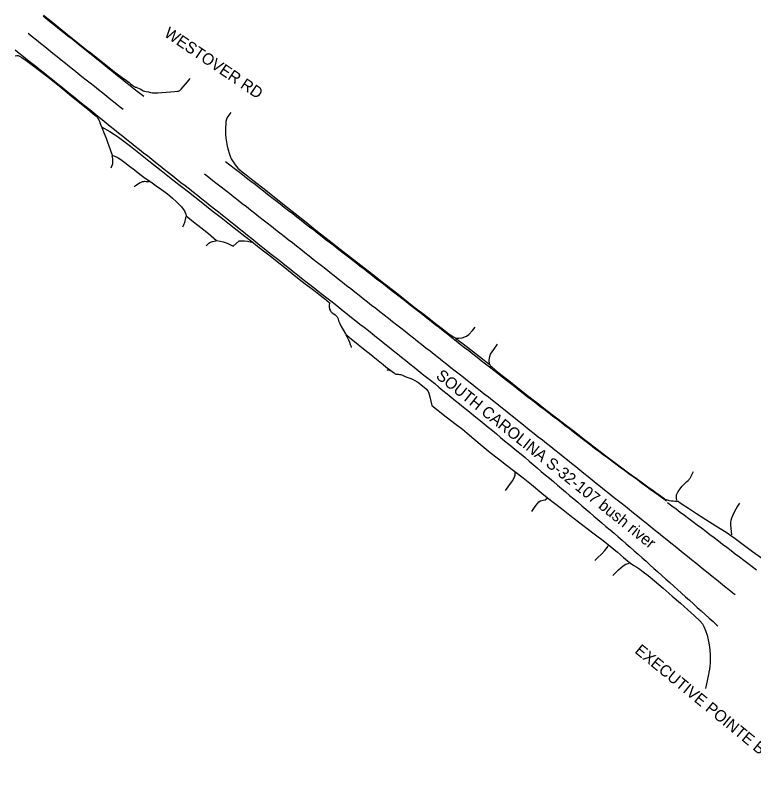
# Model space of a CAD drawing. Extents: x 1961683 to 1977751, y 798292 to 805767.
# Drawn here: x 1961690 to 1962037.9, y 800432.2 to 800788.3 of the extents above; entities that cross this region are included whole.
import ezdxf

# ---------------------------------------------------------------- set-up
doc = ezdxf.new("R2010")
doc.units = 0
for name, color, linetype in [('RD_EX_Road', 7, 'Continuous'), ('RD_EX_Road_Paint', 7, 'Continuous'), ('RD_TX_RoadID', 7, 'Continuous')]:
    doc.layers.add(name, color=color, linetype=linetype)

msp = doc.modelspace()

# ---------------------------------------------------------------- linework, layer by layer
at = {"layer": 'RD_EX_Road'}
for points in [[(1961703.41, 800788.33), (1961706.97, 800785.44), (1961713.96, 800779.79), (1961719.51, 800775.3), (1961724.42, 800771.33), (1961725.08, 800771.06), (1961732.71, 800765), (1961737.53, 800761.22), (1961740.46, 800758.97), (1961742.41, 800757.5), (1961743.68, 800756.55), (1961744.6, 800755.83), (1961745.28, 800755.29), (1961745.84, 800754.88), (1961746.34, 800754.6), (1961746.57, 800754.5), (1961747.03, 800754.38), (1961747.66, 800754.17), (1961748.45, 800753.85), (1961749.2, 800753.46), (1961749.86, 800753.02), (1961750.34, 800752.73), (1961750.52, 800752.65), (1961750.99, 800752.52), (1961751.81, 800752.35), (1961752.79, 800752.16), (1961753.78, 800751.93), (1961754.59, 800751.75), (1961755.05, 800751.69), (1961755.74, 800751.71), (1961757.24, 800751.79), (1961759.17, 800751.91), (1961761.16, 800752.05), (1961763.15, 800752.2), (1961765.07, 800752.35), (1961766.57, 800752.52), (1961767.05, 800752.62), (1961767.33, 800752.71), (1961767.56, 800752.87), (1961768.22, 800753.5), (1961769.24, 800754.66), (1961771.14, 800756.96), (1961772.45, 800758.56)], [(1961690.12, 800769.16), (1961690.78, 800769.36), (1961691.04, 800769.39), (1961691.27, 800769.38), (1961691.5, 800769.32), (1961692.15, 800769.03), (1961693.16, 800768.44), (1961695.19, 800767.05), (1961698.29, 800764.8), (1961702.19, 800761.83), (1961706.78, 800758.21), (1961711.65, 800754.29), (1961716.64, 800750.22), (1961721.26, 800746.47), (1961725.26, 800743.26), (1961727.62, 800741.32), (1961728.11, 800740.87), (1961728.61, 800740.3), (1961729.02, 800739.67), (1961729.39, 800738.99), (1961729.74, 800738.26), (1961730.15, 800737.28), (1961730.73, 800735.82), (1961734.57, 800733.53), (1961736.88, 800732.13), (1961738.75, 800730.89), (1961741.25, 800729.07), (1961744.43, 800726.64), (1961748.32, 800723.57), (1961753.06, 800719.79), (1961758.81, 800715.22), (1961765.14, 800710.22), (1961771.61, 800705.16), (1961777.67, 800700.42), (1961782.74, 800696.44), (1961787.08, 800693.03), (1961790.95, 800690.01), (1961794.57, 800687.19), (1961798.15, 800684.36), (1961801.44, 800681.74), (1961804.22, 800679.57), (1961806.94, 800677.46), (1961810.07, 800675), (1961813.46, 800672.31), (1961817, 800669.48), (1961820.51, 800666.67), (1961823.83, 800664.03), (1961826.68, 800661.83), (1961828.8, 800660.35), (1961830.74, 800658.96), (1961833.07, 800657.05), (1961835.66, 800654.89), (1961837.91, 800653.13), (1961838.02, 800653.05), (1961838.07, 800652.95), (1961838.07, 800652.86), (1961837.95, 800651.72), (1961837.94, 800651.23), (1961837.98, 800650.8), (1961838.05, 800650.39), (1961838.16, 800649.99), (1961838.5, 800649.21), (1961838.73, 800648.84), (1961839, 800648.5), (1961839.33, 800648.19), (1961840.08, 800647.67), (1961840.71, 800647.23), (1961841.18, 800646.87), (1961841.54, 800646.5), (1961841.68, 800646.32), (1961841.82, 800646.09), (1961842.09, 800645.42), (1961842.39, 800644.45), (1961842.89, 800643.26), (1961843.62, 800641.84), (1961844.53, 800640.17), (1961845.57, 800638.33), (1961846.3, 800637.67), (1961847.27, 800636.84), (1961848.47, 800635.84), (1961849.92, 800634.66), (1961851.52, 800633.37), (1961853.18, 800632.03), (1961854.91, 800630.64), (1961856.71, 800629.19), (1961858.5, 800627.76), (1961860.19, 800626.41), (1961861.79, 800625.13), (1961863.29, 800623.93), (1961864.67, 800622.84), (1961865.88, 800621.89), (1961866.92, 800621.09), (1961867.8, 800620.44), (1961868.49, 800619.96), (1961869.04, 800619.56), (1961869.36, 800619.36), (1961869.47, 800619.32), (1961869.59, 800619.3), (1961869.72, 800619.29), (1961870.01, 800619.3), (1961870.31, 800619.31), (1961870.63, 800619.31), (1961871.09, 800619.25), (1961871.7, 800619.13), (1961872.45, 800618.86), (1961873.34, 800618.45), (1961874.53, 800618), (1961875.95, 800617.51), (1961877.2, 800616.97), (1961878.22, 800616.39), (1961879.16, 800615.82), (1961880.08, 800615.22), (1961881.29, 800614.34), (1961882.74, 800613.22), (1961883.78, 800612.25), (1961884.1, 800611.84), (1961884.56, 800611.12), (1961884.93, 800610.45), (1961885.41, 800608.67), (1961886.23, 800604.62), (1961893.04, 800599.28), (1961897.8, 800595.6), (1961900.66, 800593.41), (1961901.78, 800592.56), (1961902.98, 800591.56), (1961906.07, 800588.96), (1961910.03, 800585.65), (1961913.82, 800582.53), (1961917.59, 800579.53), (1961921.49, 800576.55), (1961925.42, 800573.55), (1961929.3, 800570.48), (1961933.17, 800567.35), (1961937.07, 800564.18), (1961940.76, 800561.2), (1961944.01, 800558.66), (1961947.32, 800556.1), (1961951.24, 800553.04), (1961955.41, 800549.8), (1961959.47, 800546.67), (1961963.33, 800543.72), (1961966.91, 800540.99), (1961970.32, 800538.33), (1961973.7, 800535.54), (1961976.56, 800533.11), (1961978.45, 800531.49), (1961979.88, 800530.35), (1961981.38, 800529.37), (1961982.87, 800528.46), (1961984.25, 800527.55), (1961985.87, 800526.36), (1961988.1, 800524.59), (1961991.14, 800522.07), (1961995.19, 800518.62), (1961999.52, 800514.9), (1962003.36, 800511.56), (1962006.81, 800508.5), (1962010, 800505.59), (1962012.46, 800503.23), (1962013.73, 800501.82), (1962014.07, 800501.27), (1962014.43, 800500.57), (1962015.17, 800498.73), (1962015.87, 800496.56), (1962016.41, 800494.33), (1962016.82, 800492.01), (1962017.12, 800489.61), (1962017.31, 800487.29), (1962017.35, 800485.22), (1962017.28, 800483.42), (1962017.15, 800481.9), (1962016.97, 800480.5), (1962016.73, 800479.04), (1962016.51, 800477.9), (1962016.42, 800477.44), (1962016.07, 800475.86), (1962015.08, 800471.33)], [(1961791.57, 800742.58), (1961790.18, 800740.55), (1961789.77, 800739.83), (1961789.55, 800739.29), (1961789.34, 800738.28), (1961789.19, 800737.01), (1961789.11, 800735.54), (1961789.08, 800733.94), (1961789.13, 800732.22), (1961789.27, 800730.39), (1961789.53, 800728.52), (1961789.91, 800726.67), (1961790.37, 800724.92), (1961790.85, 800723.31), (1961791.35, 800721.91), (1961791.85, 800720.76), (1961792.4, 800719.75), (1961793.02, 800718.75), (1961793.67, 800717.82), (1961794.3, 800717.02), (1961794.98, 800716.29), (1961795.78, 800715.58), (1961797, 800714.61), (1961798.91, 800713.11), (1961801.97, 800710.71), (1961806.64, 800707.05), (1961811.95, 800702.88), (1961816.91, 800698.93), (1961821.84, 800694.99), (1961827.06, 800690.82), (1961832.45, 800686.55), (1961837.88, 800682.29), (1961843.13, 800678.19), (1961847.99, 800674.42), (1961852.9, 800670.6), (1961858.29, 800666.41), (1961863.74, 800662.16), (1961868.83, 800658.18), (1961873.7, 800654.37), (1961878.49, 800650.62), (1961883.23, 800646.91), (1961887.95, 800643.24), (1961891.88, 800640.2), (1961894.26, 800638.4), (1961895.62, 800637.43), (1961896.47, 800636.88), (1961897.05, 800636.54), (1961897.59, 800636.2), (1961898.71, 800635.38), (1961901.04, 800633.6), (1961904.42, 800630.98), (1961908.71, 800627.65), (1961912.28, 800624.85), (1961913.52, 800623.83), (1961913.62, 800623.67), (1961913.78, 800623.45), (1961914.47, 800622.81), (1961916.15, 800621.41), (1961918.81, 800619.24), (1961922.46, 800616.31), (1961926.75, 800612.93), (1961931.32, 800609.37), (1961935.95, 800605.78), (1961940.44, 800602.31), (1961944.95, 800598.84), (1961949.64, 800595.24), (1961954.01, 800591.88), (1961957.54, 800589.13), (1961960.74, 800586.64), (1961964.09, 800584.05), (1961967.61, 800581.37), (1961971.31, 800578.58), (1961975.1, 800575.75), (1961978.89, 800572.96), (1961982.43, 800570.39), (1961985.46, 800568.19), (1961987.96, 800566.38), (1961989.89, 800565), (1961991.69, 800563.71), (1961993.82, 800562.17), (1961995.57, 800560.91), (1961996.23, 800560.43), (1961996.29, 800560.39), (1961996.35, 800560.36), (1961996.41, 800560.34), (1961996.6, 800560.29), (1961997.16, 800560.16), (1961998.07, 800559.96), (1961999.01, 800559.78), (1961999.94, 800559.66), (1962000.78, 800559.59), (1962001.51, 800559.59), (1962001.96, 800559.59), (1962002.06, 800559.59), (1962002.14, 800559.59), (1962002.21, 800559.57), (1962002.28, 800559.53), (1962002.62, 800559.32), (1962004.22, 800558.24), (1962007.19, 800556.28), (1962010.94, 800553.83), (1962015.34, 800551.02), (1962020.02, 800548.04), (1962024.82, 800544.96), (1962029.1, 800542.01), (1962032.9, 800539.14), (1962037.24, 800535.96), (1962042.18, 800532.46)], [(1961730.94, 800735.45), (1961732.03, 800732.67), (1961732.88, 800730.41), (1961733.58, 800728.54), (1961734.2, 800726.89), (1961734.87, 800725.03), (1961735.76, 800722.47), (1961737.3, 800721.81), (1961738.51, 800721.19), (1961739.83, 800720.34), (1961741.69, 800719), (1961743.91, 800717.31), (1961746.32, 800715.45), (1961748.82, 800713.53), (1961751.34, 800711.66), (1961753.87, 800709.83), (1961756.41, 800708.05), (1961759.02, 800706.2), (1961761.73, 800704.19), (1961764.17, 800702.24), (1961765.93, 800700.63), (1961767.26, 800699.27), (1961768.36, 800698.07), (1961769.22, 800697.05), (1961769.8, 800696.2), (1961770.02, 800695.77), (1961770.43, 800694.61), (1961770.61, 800693.87), (1961774.06, 800691.07), (1961777.49, 800688.42), (1961781.05, 800685.59), (1961784.91, 800682.2), (1961786.56, 800681.99), (1961787.99, 800681.7), (1961789.85, 800681), (1961792.76, 800679.58), (1961795.61, 800682.09), (1961796.99, 800682.16), (1961798.1, 800682.13), (1961799.42, 800681.93), (1961801.42, 800681.5)], [(1961735.26, 800716.42), (1961735.62, 800717.21), (1961735.99, 800718.29), (1961736.08, 800718.76), (1961736.12, 800719.24), (1961736.12, 800719.74), (1961735.99, 800720.74), (1961735.82, 800721.65), (1961735.73, 800722.07)], [(1961746.15, 800707.49), (1961746.79, 800708.07), (1961747.51, 800708.65), (1961748.2, 800709.13), (1961748.86, 800709.5), (1961749.47, 800709.78), (1961750.05, 800709.96), (1961750.62, 800710.07), (1961750.9, 800710.11), (1961751.76, 800710.1), (1961753.23, 800709.95)], [(1961769.02, 800688.75), (1961769.37, 800689.37), (1961769.69, 800690.06), (1961769.95, 800690.78), (1961770.14, 800691.46), (1961770.25, 800692.11), (1961770.36, 800692.94), (1961770.43, 800693.44)], [(1961780.03, 800679.74), (1961780.68, 800680.41), (1961781.26, 800680.96), (1961781.8, 800681.35), (1961782.06, 800681.49), (1961782.92, 800681.78), (1961784.48, 800682.15)], [(1961897.79, 800636.36), (1961898.95, 800636.25), (1961900.63, 800636.49), (1961902.61, 800637.31), (1961903.62, 800638.02), (1961905.47, 800639.93), (1961906.75, 800641.5)], [(1961845.84, 800637.82), (1961846.39, 800636.78), (1961846.97, 800635.57), (1961847.46, 800634.43), (1961847.89, 800633.34), (1961848.21, 800632.3), (1961848.29, 800631.94)], [(1961913.38, 800624.22), (1961913.31, 800625.9), (1961913.55, 800627.6), (1961913.94, 800628.78), (1961915.42, 800630.97), (1961917.15, 800633.43)], [(1961867.54, 800620.58), (1961867.07, 800620.83), (1961866.43, 800621.12), (1961866.19, 800621.19), (1961866.01, 800621.23), (1961865.85, 800621.23), (1961865.66, 800621.21), (1961865.45, 800621.16), (1961865.07, 800621.01)], [(1961921.01, 800564.64), (1961924.22, 800569.16), (1961925.2, 800570.89), (1961925.45, 800571.75), (1961925.48, 800573.19)], [(1962001.65, 800560.07), (1962001.5, 800560.85), (1962001.44, 800561.54), (1962001.45, 800562.13), (1962001.55, 800562.63), (1962001.73, 800563.11), (1962002.32, 800564.2), (1962003.15, 800565.44), (1962003.95, 800566.43), (1962004.66, 800567.15), (1962005.31, 800567.78), (1962005.9, 800568.34), (1962006.43, 800568.85), (1962006.92, 800569.3), (1962007.38, 800569.79), (1962007.61, 800570.05), (1962007.9, 800570.47), (1962008.84, 800572.24), (1962009.49, 800573.59)], [(1961933.32, 800554.66), (1961934.97, 800557.05), (1961936.61, 800559.21), (1961937.41, 800559.73), (1961938.65, 800560.04), (1961939.66, 800560.13), (1961940.6, 800560.95)], [(1962031.11, 800558.6), (1962030.22, 800557.2), (1962029.42, 800555.79), (1962028.69, 800554.37), (1962028.02, 800552.94), (1962027.47, 800551.61), (1962027.11, 800550.49), (1962026.92, 800549.47), (1962026.89, 800548.39), (1962027.03, 800546.67), (1962027.35, 800543.69)], [(1961963, 800531.72), (1961964.3, 800532.98), (1961966.26, 800534.84), (1961967.74, 800536.3), (1961968.94, 800537.97), (1961969.38, 800538.78)], [(1961971.44, 800524.66), (1961974.18, 800527.18), (1961976.4, 800529.11), (1961977.62, 800529.92), (1961979.23, 800530.43)]]:
    msp.add_lwpolyline(points, dxfattribs=at)
at = {"layer": 'RD_EX_Road_Paint'}
for points in [[(1961703.19, 800788.06), (1961705.13, 800786.49), (1961707.08, 800784.92), (1961709.03, 800783.36), (1961710.98, 800781.79), (1961712.93, 800780.23), (1961714.88, 800778.66), (1961716.83, 800777.1), (1961718.78, 800775.53), (1961720.73, 800773.97), (1961722.68, 800772.4), (1961724.62, 800770.83), (1961726.57, 800769.27), (1961728.53, 800767.71), (1961730.49, 800766.16), (1961732.44, 800764.6), (1961734.4, 800763.04), (1961736.36, 800761.49), (1961738.31, 800759.93), (1961740.27, 800758.38), (1961742.23, 800756.82), (1961744.18, 800755.26), (1961746.14, 800753.71), (1961748.1, 800752.15), (1961750.05, 800750.59), (1961750.62, 800750.14)], [(1961696.16, 800779.85), (1961698.11, 800778.29), (1961700.06, 800776.72), (1961702.01, 800775.15), (1961703.96, 800773.59), (1961705.9, 800772.02), (1961707.85, 800770.45), (1961709.8, 800768.89), (1961711.75, 800767.32), (1961713.7, 800765.76), (1961715.65, 800764.2), (1961717.61, 800762.64), (1961719.56, 800761.08), (1961721.51, 800759.52), (1961723.46, 800757.95), (1961725.41, 800756.39), (1961727.37, 800754.83), (1961729.32, 800753.27), (1961731.27, 800751.71), (1961733.23, 800750.15), (1961735.18, 800748.59), (1961737.14, 800747.03), (1961739.09, 800745.47), (1961740.91, 800744.02)], [(1961690.04, 800772.06), (1961691.98, 800770.48), (1961693.92, 800768.91), (1961695.88, 800767.35), (1961697.83, 800765.8), (1961699.79, 800764.24), (1961701.75, 800762.69), (1961703.7, 800761.13), (1961705.65, 800759.56), (1961707.61, 800758.01), (1961709.57, 800756.45), (1961711.51, 800754.87), (1961713.44, 800753.3), (1961715.38, 800751.71), (1961717.31, 800750.13), (1961719.25, 800748.55), (1961721.2, 800746.98), (1961723.16, 800745.44), (1961725.14, 800743.9), (1961727.08, 800742.33), (1961729.02, 800740.76), (1961730.96, 800739.18), (1961732.91, 800737.6), (1961734.86, 800736.04), (1961736.81, 800734.48), (1961738.78, 800732.94), (1961740.75, 800731.41), (1961742.69, 800729.83), (1961744.63, 800728.25), (1961746.59, 800726.69), (1961748.54, 800725.13), (1961750.5, 800723.58), (1961752.46, 800722.03), (1961754.42, 800720.47), (1961756.37, 800718.92), (1961758.33, 800717.36), (1961760.29, 800715.81), (1961762.26, 800714.27), (1961764.23, 800712.73), (1961766.19, 800711.18), (1961768.15, 800709.62), (1961770.12, 800708.09), (1961772.09, 800706.55), (1961774.05, 800704.99), (1961776, 800703.43), (1961777.97, 800701.89), (1961779.94, 800700.35), (1961781.9, 800698.8), (1961783.85, 800697.24), (1961785.8, 800695.68), (1961787.75, 800694.11), (1961789.71, 800692.56), (1961791.68, 800691.02), (1961793.63, 800689.45), (1961795.57, 800687.88), (1961797.53, 800686.33), (1961799.49, 800684.78), (1961801.44, 800683.22), (1961803.39, 800681.65), (1961805.35, 800680.1), (1961807.31, 800678.54), (1961809.26, 800676.98), (1961811.22, 800675.43), (1961813.18, 800673.88), (1961815.15, 800672.33), (1961817.1, 800670.77), (1961819.05, 800669.21), (1961821.03, 800667.69), (1961823.02, 800666.17), (1961824.96, 800664.6), (1961826.91, 800663.03), (1961828.88, 800661.49), (1961830.85, 800659.95), (1961832.81, 800658.41), (1961834.78, 800656.86), (1961836.76, 800655.33), (1961838.73, 800653.79), (1961840.68, 800652.23), (1961842.64, 800650.68), (1961844.59, 800649.11), (1961846.54, 800647.55), (1961848.48, 800645.97), (1961850.43, 800644.41), (1961852.43, 800642.91), (1961854.42, 800641.4), (1961856.37, 800639.83), (1961858.32, 800638.27), (1961860.28, 800636.71), (1961862.23, 800635.16), (1961864.2, 800633.61), (1961866.16, 800632.06), (1961868.12, 800630.5), (1961870.08, 800628.95), (1961872.03, 800627.39), (1961873.98, 800625.83), (1961875.93, 800624.26), (1961877.88, 800622.7), (1961879.83, 800621.13), (1961881.78, 800619.57), (1961883.74, 800618.01), (1961885.69, 800616.46), (1961887.63, 800614.88), (1961889.57, 800613.3), (1961891.51, 800611.73), (1961893.45, 800610.15), (1961895.4, 800608.58), (1961897.34, 800607.01), (1961899.29, 800605.45), (1961901.24, 800603.87), (1961903.17, 800602.29), (1961905.11, 800600.71), (1961907.05, 800599.13), (1961908.98, 800597.55), (1961910.91, 800595.96), (1961912.84, 800594.38), (1961914.77, 800592.79), (1961916.71, 800591.21), (1961918.63, 800589.61), (1961920.56, 800588.02), (1961922.5, 800586.44), (1961924.43, 800584.86), (1961926.35, 800583.26), (1961928.27, 800581.65), (1961930.18, 800580.05), (1961932.1, 800578.44), (1961934, 800576.82), (1961935.91, 800575.2), (1961937.81, 800573.59), (1961939.72, 800571.97), (1961941.65, 800570.38), (1961943.57, 800568.78), (1961945.46, 800567.15), (1961947.36, 800565.52), (1961949.26, 800563.9), (1961951.17, 800562.28), (1961953.07, 800560.67), (1961954.98, 800559.05), (1961956.87, 800557.42), (1961958.77, 800555.79), (1961960.67, 800554.17), (1961962.57, 800552.55), (1961964.47, 800550.93), (1961966.38, 800549.3), (1961968.28, 800547.68), (1961970.18, 800546.06), (1961972.08, 800544.44), (1961973.97, 800542.81), (1961975.85, 800541.16), (1961977.73, 800539.51), (1961979.61, 800537.86), (1961981.48, 800536.21), (1961983.37, 800534.57), (1961985.25, 800532.93), (1961987.13, 800531.27), (1961989, 800529.62), (1961990.87, 800527.96), (1961992.73, 800526.3), (1961994.58, 800524.62), (1961996.43, 800522.94), (1961998.3, 800521.27), (1962000.16, 800519.61), (1962002.01, 800517.94), (1962003.87, 800516.27), (1962005.72, 800514.59), (1962007.57, 800512.91), (1962009.43, 800511.24), (1962011.28, 800509.57), (1962013.14, 800507.89), (1962014.99, 800506.22), (1962016.85, 800504.55), (1962018.71, 800502.88), (1962020.56, 800501.21), (1962020.93, 800500.88)], [(1961789.17, 800719.43), (1961791.15, 800717.9), (1961793.12, 800716.37), (1961795.1, 800714.83), (1961797.07, 800713.3), (1961799.05, 800711.77), (1961801.02, 800710.23), (1961803, 800708.7), (1961804.97, 800707.17), (1961806.95, 800705.64), (1961808.92, 800704.1), (1961810.89, 800702.57), (1961812.87, 800701.03), (1961814.84, 800699.5), (1961816.81, 800697.96), (1961818.78, 800696.43), (1961820.76, 800694.89), (1961822.73, 800693.35), (1961824.7, 800691.82), (1961826.68, 800690.28), (1961828.65, 800688.75), (1961830.63, 800687.22), (1961832.61, 800685.7), (1961834.59, 800684.17), (1961836.57, 800682.64), (1961838.54, 800681.11), (1961840.52, 800679.58), (1961842.5, 800678.05), (1961844.48, 800676.52), (1961846.46, 800674.99), (1961848.43, 800673.46), (1961850.41, 800671.93), (1961852.39, 800670.4), (1961854.36, 800668.87), (1961856.34, 800667.34), (1961858.32, 800665.81), (1961860.29, 800664.28), (1961862.27, 800662.75), (1961864.25, 800661.22), (1961866.22, 800659.69), (1961868.19, 800658.15), (1961870.17, 800656.62), (1961872.14, 800655.09), (1961874.12, 800653.55), (1961876.09, 800652.02), (1961878.06, 800650.48), (1961880.03, 800648.94), (1961882, 800647.4), (1961883.97, 800645.86), (1961885.94, 800644.32), (1961887.91, 800642.79), (1961889.88, 800641.24), (1961891.84, 800639.69), (1961893.8, 800638.14), (1961895.75, 800636.58), (1961897.71, 800635.03), (1961899.67, 800633.48), (1961901.65, 800631.94), (1961903.62, 800630.41), (1961905.6, 800628.88), (1961907.57, 800627.35), (1961909.55, 800625.82), (1961911.52, 800624.28), (1961913.5, 800622.75), (1961915.47, 800621.22), (1961917.44, 800619.68), (1961919.41, 800618.13), (1961921.37, 800616.59), (1961923.34, 800615.05), (1961925.31, 800613.51), (1961927.27, 800611.96), (1961929.24, 800610.42), (1961931.23, 800608.91), (1961933.22, 800607.4), (1961935.21, 800605.88), (1961937.19, 800604.36), (1961939.17, 800602.84), (1961941.16, 800601.32), (1961943.14, 800599.8), (1961945.13, 800598.28), (1961947.11, 800596.76), (1961949.09, 800595.24), (1961951.07, 800593.71), (1961953.05, 800592.19), (1961955.03, 800590.66), (1961957.01, 800589.14), (1961958.99, 800587.61), (1961960.97, 800586.09), (1961962.95, 800584.56), (1961964.95, 800583.06), (1961966.96, 800581.58), (1961968.96, 800580.09), (1961970.97, 800578.6), (1961972.98, 800577.11), (1961974.99, 800575.63), (1961977, 800574.14), (1961979.01, 800572.65), (1961981.03, 800571.18), (1961983.05, 800569.71), (1961985.07, 800568.24), (1961987.08, 800566.77), (1961989.1, 800565.3), (1961991.12, 800563.82), (1961993.14, 800562.35), (1961996.81, 800559.68)], [(1961779.27, 800713.62), (1961781.23, 800712.08), (1961783.2, 800710.54), (1961785.17, 800708.99), (1961787.13, 800707.45), (1961789.1, 800705.91), (1961791.07, 800704.36), (1961793.03, 800702.82), (1961795, 800701.28), (1961796.97, 800699.74), (1961798.94, 800698.2), (1961800.91, 800696.66), (1961802.88, 800695.12), (1961804.85, 800693.58), (1961806.82, 800692.04), (1961808.79, 800690.5), (1961810.76, 800688.96), (1961812.73, 800687.42), (1961814.7, 800685.88), (1961816.67, 800684.34), (1961818.63, 800682.8), (1961820.6, 800681.26), (1961822.57, 800679.72), (1961824.54, 800678.18), (1961826.51, 800676.64), (1961828.47, 800675.09), (1961830.43, 800673.53), (1961832.38, 800671.98), (1961834.34, 800670.42), (1961836.3, 800668.87), (1961838.26, 800667.31), (1961840.21, 800665.76), (1961842.18, 800664.21), (1961844.15, 800662.67), (1961846.12, 800661.13), (1961848.09, 800659.59), (1961850.06, 800658.05), (1961852.03, 800656.51), (1961853.99, 800654.97), (1961855.96, 800653.43), (1961857.93, 800651.89), (1961859.9, 800650.34), (1961861.86, 800648.8), (1961863.83, 800647.25), (1961865.79, 800645.71), (1961867.76, 800644.16), (1961869.73, 800642.62), (1961871.69, 800641.08), (1961873.66, 800639.53), (1961875.62, 800637.99), (1961877.59, 800636.44), (1961879.56, 800634.9), (1961881.52, 800633.36), (1961883.49, 800631.81), (1961885.45, 800630.27), (1961887.42, 800628.72), (1961889.38, 800627.18), (1961891.35, 800625.63), (1961893.31, 800624.09), (1961895.28, 800622.54), (1961897.24, 800620.99), (1961899.2, 800619.45), (1961901.17, 800617.9), (1961903.13, 800616.35), (1961905.09, 800614.8), (1961907.05, 800613.25), (1961909.02, 800611.7), (1961910.98, 800610.15), (1961912.94, 800608.61), (1961914.9, 800607.06), (1961916.86, 800605.51), (1961918.82, 800603.95), (1961920.77, 800602.39), (1961922.72, 800600.83), (1961924.68, 800599.27), (1961926.63, 800597.71), (1961928.58, 800596.15), (1961930.54, 800594.59), (1961932.49, 800593.03), (1961934.45, 800591.48), (1961936.41, 800589.93), (1961938.37, 800588.38), (1961940.33, 800586.82), (1961942.29, 800585.27), (1961944.24, 800583.72), (1961946.2, 800582.17), (1961948.16, 800580.62), (1961950.12, 800579.06), (1961952.07, 800577.5), (1961954.01, 800575.93), (1961955.96, 800574.36), (1961957.91, 800572.79), (1961959.85, 800571.22), (1961961.8, 800569.66), (1961963.74, 800568.09), (1961965.69, 800566.52), (1961967.64, 800564.95), (1961969.6, 800563.4), (1961971.55, 800561.84), (1961973.5, 800560.28), (1961975.45, 800558.72), (1961977.4, 800557.15), (1961979.35, 800555.59), (1961981.3, 800554.03), (1961983.25, 800552.46), (1961985.19, 800550.9), (1961987.14, 800549.34), (1961989.1, 800547.78), (1961991.05, 800546.22), (1961993, 800544.66), (1961994.95, 800543.1), (1961996.9, 800541.54), (1961998.85, 800539.98), (1962000.8, 800538.42), (1962002.75, 800536.86), (1962004.71, 800535.3), (1962006.65, 800533.73), (1962008.59, 800532.16), (1962010.54, 800530.59), (1962012.48, 800529.02), (1962014.43, 800527.45), (1962016.37, 800525.88), (1962018.32, 800524.31), (1962020.26, 800522.74), (1962022.2, 800521.18), (1962024.15, 800519.61), (1962026.09, 800518.04), (1962028.04, 800516.47), (1962029.08, 800515.63)], [(1961997.28, 800558.98), (1961999.25, 800557.45), (1962001.26, 800555.95), (1962003.26, 800554.46), (1962005.26, 800552.96), (1962007.26, 800551.47), (1962009.26, 800549.97), (1962011.26, 800548.47), (1962013.25, 800546.96), (1962015.25, 800545.46), (1962017.24, 800543.95), (1962019.23, 800542.44), (1962021.22, 800540.93), (1962023.21, 800539.41), (1962025.19, 800537.9), (1962027.18, 800536.38), (1962029.16, 800534.86), (1962031.15, 800533.34), (1962033.14, 800531.83), (1962035.13, 800530.33), (1962037.13, 800528.83), (1962039.13, 800527.33)]]:
    msp.add_lwpolyline(points, dxfattribs=at)

# ---------------------------------------------------------------- texts
at = {"layer": 'RD_TX_RoadID'}
for s, rotation, p in [('WESTOVER RD', 326.0371, (1961759.79, 800778.65)), ('SOUTH CAROLINA S-32-107 bush river', 321.3568, (1961887.82, 800617.82)), ('EXECUTIVE POINTE BLVD', 320.6752, (1961981.44, 800488.52))]:
    msp.add_text(s, height=5.4, rotation=rotation, dxfattribs=at).set_placement(p)

doc.saveas('drawing.dxf')
